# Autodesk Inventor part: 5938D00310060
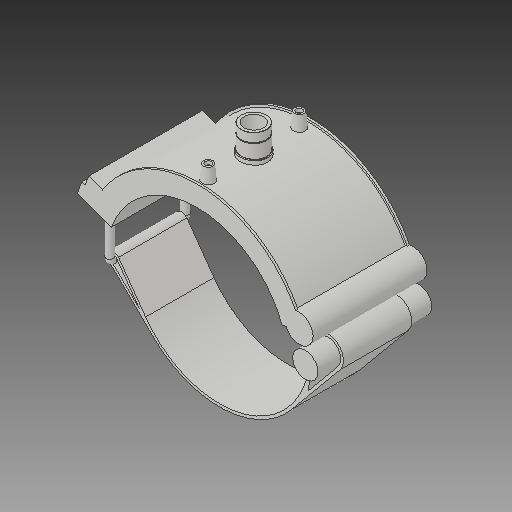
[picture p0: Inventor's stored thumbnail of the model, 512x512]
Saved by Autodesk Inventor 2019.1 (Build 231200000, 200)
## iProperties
Created: 2017-07
Part Number: 5938D00310060
Material: Generic
Description: PLASSON TRANSITION SADDLE 10''DIPS x 1"NPT
Document SubType Name: Modeling
Designer: KIM
Density: 1 g/cm^3
Appearance: Default
Author: KIM
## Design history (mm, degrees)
derived "5938D.ipt"
feature "Solid1::5938D.ipt"
tag "TaggingFeature1"
body "Solid1"
other parameters: "d0" = 280.6, "d1" = 336.72, "d2" = 450.85, "d3" = 70.15, "d4" = 176.022, "d5" = 0, "d40" = 175.0944, "d41" = 42.4074, "d43" = 0, "d45" = 0, "d47" = 210.27, "d48" = 39.3783, "d50" = 0, "d78" = 190.36, "d79" = 15, "d80" = 70.4088, "d82" = 5 deg, "d84" = 4, "d85" = 14, "d86" = 0, "d87" = 3, "d88" = 0, "d96" = 343.4544, "d97" = 3.52044, "d98" = 0, "d102" = 0.90873, "d103" = 30.291, "d104" = 25.146, "d105" = 0, "d106" = 24.2328, "d108" = 0, "d109" = -13.97, "d111" = 0.5, "d112" = 0.5, "d113" = 0, "d114" = 0.5, "d117" = 0.30291, "d120" = 140 deg, "d121" = 24.228, "d122" = 20 deg, "d123" = 1346.88, "d124" = 202.032, "d126" = 0, "d143" = 289.018, "d145" = 43.16923, "d149" = 4.209, "d150" = 47.48615, "d153" = 176.022, "d154" = 0, "d156" = 168.36, "d157" = 160 deg, "d159" = 11.224, "d161" = 4.209, "d162" = 105.6132, "d163" = 0, "d164" = 140.3, "d167" = 28.06, "d168" = 164.25366, "d170" = 4.209, "d172" = 0, "d173" = 1, "d175" = 140.3, "d176" = 20 deg, "d177" = 19.642, "d178" = 56.12, "d180" = 0, "d183" = 22.448, "d184" = 15.7136, "d185" = 57.20715, "d186" = 57.20715, "d187" = 168.36, "d188" = 16.836, "d189" = 19.642, "d190" = 0, "d191" = 202.032, "d193" = 11.224, "d194" = 5.7523, "d195" = 90 deg, "d197" = 0, "d199" = 0, "d_" = 280.6, "B_" = 180.34, "H_" = 41.91, "L_" = 176.022, "d_t" = 6, "G_" = 30.291, "d148" = 4.209, "d160" = 4.209, "d169" = 4.209, "d192" = 11.224
